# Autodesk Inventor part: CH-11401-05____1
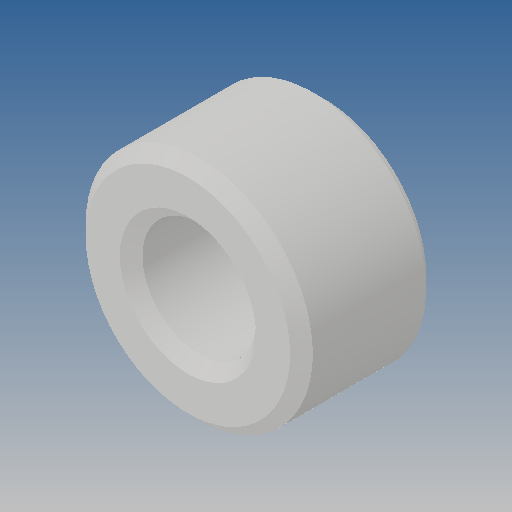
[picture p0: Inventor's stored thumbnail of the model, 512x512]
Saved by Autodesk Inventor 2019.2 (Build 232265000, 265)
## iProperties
Created: 2012-09
Part Number: CH-11401-05____1
Material: Ogólny
Document SubType Name: Modeling
Designer: CADENGINEERING4
Density: 1 g/cm^3
Appearance: Domyślna
Author: CADENGINEERING4
Revision Number: ÈÎºÎ
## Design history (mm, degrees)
feature "NONE"
node "Bryła1"
